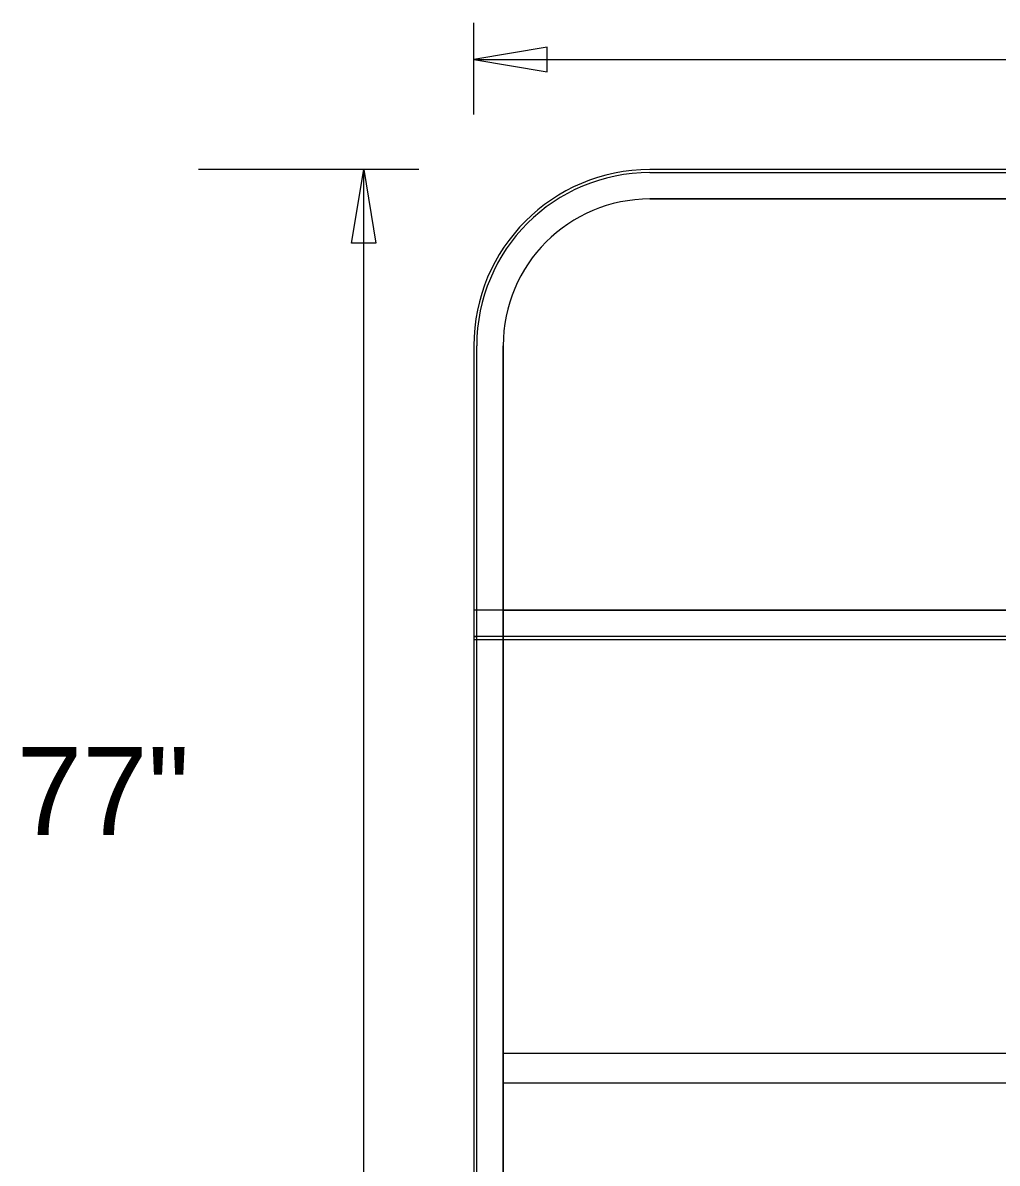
# Model space of a CAD drawing. Extents: x 119523 to 121850, y -23542 to -19972.
# Drawn here: x 120147.5 to 120213.9, y -22898.6 to -22820.9 of the extents above; entities that cross this region are included whole.
import ezdxf

# ---------------------------------------------------------------- set-up
doc = ezdxf.new("R2010")
doc.units = 0
for name, color, linetype in [('GSBWFill', 7, 'Continuous'), ('GSColorFill', 7, 'Continuous'), ('GSDims', 7, 'Continuous'), ('GSOutline', 7, 'Continuous')]:
    doc.layers.add(name, color=color, linetype=linetype)

msp = doc.modelspace()

# ---------------------------------------------------------------- linework, layer by layer
at = {"layer": 'GSBWFill'}
for p, q in [((120424.249, -22830.872), (120190.249, -22830.872)), ((120424.249, -22830.872), (120190.249, -22830.872)), ((120190.249, -22832.872), (120424.249, -22832.872)), ((120190.249, -22832.872), (120424.249, -22832.872)), ((120178.249, -22842.872), (120178.249, -22974.872)), ((120178.249, -22842.872), (120178.249, -22860.852)), ((120180.249, -22974.872), (120180.249, -22842.872)), ((120180.249, -22860.852), (120180.249, -22842.872)), ((120178.249, -22860.852), (120180.249, -22860.852)), ((120434.249, -22860.872), (120178.249, -22860.872)), ((120178.249, -22860.872), (120178.249, -22862.872)), ((120178.249, -22862.872), (120436.249, -22862.872)), ((120434.249, -22891.075), (120180.249, -22891.075)), ((120180.249, -22891.075), (120180.249, -22893.075)), ((120180.249, -22893.075), (120434.249, -22893.075))]:
    msp.add_line(p, q, dxfattribs=at)
for radius in [12, 12, 10, 10]:
    msp.add_arc((120190.249, -22842.872), radius, 90, 180, dxfattribs=at)
at = {"layer": 'GSColorFill'}
for p, q in [((120424.249, -22830.872), (120190.249, -22830.872)), ((120424.249, -22830.872), (120190.249, -22830.872)), ((120424.249, -22830.872), (120190.249, -22830.872)), ((120424.249, -22830.872), (120190.249, -22830.872)), ((120424.249, -22830.872), (120190.249, -22830.872)), ((120424.249, -22830.872), (120190.249, -22830.872)), ((120190.249, -22831.072), (120424.249, -22831.072)), ((120190.249, -22831.072), (120424.249, -22831.072)), ((120190.249, -22832.872), (120424.249, -22832.872)), ((120190.249, -22832.872), (120424.249, -22832.872)), ((120178.249, -22842.872), (120178.249, -22974.872)), ((120178.249, -22842.872), (120178.249, -22974.872)), ((120178.249, -22842.872), (120178.249, -22974.872)), ((120178.249, -22842.872), (120178.249, -22862.872)), ((120178.249, -22842.872), (120178.249, -22860.852)), ((120178.249, -22842.872), (120178.249, -22862.67)), ((120178.449, -22974.872), (120178.449, -22842.872)), ((120178.449, -22862.67), (120178.449, -22842.872)), ((120180.249, -22974.872), (120180.249, -22842.872)), ((120180.249, -22860.852), (120180.249, -22842.872)), ((120178.249, -22860.852), (120180.249, -22860.852)), ((120434.249, -22860.872), (120178.249, -22860.872)), ((120178.249, -22860.872), (120178.249, -22862.872)), ((120178.249, -22862.67), (120178.449, -22862.67)), ((120436.049, -22862.672), (120178.249, -22862.672)), ((120178.249, -22862.672), (120178.249, -22862.872)), ((120178.249, -22862.872), (120436.249, -22862.872)), ((120178.249, -22862.872), (120436.249, -22862.872)), ((120178.249, -22862.872), (120436.249, -22862.872)), ((120434.249, -22891.075), (120180.249, -22891.075)), ((120180.249, -22891.075), (120180.249, -22893.075)), ((120180.249, -22893.075), (120434.249, -22893.075))]:
    msp.add_line(p, q, dxfattribs=at)
for radius in [12, 12, 12, 12, 12, 12, 11.8, 11.8, 10, 10]:
    msp.add_arc((120190.249, -22842.872), radius, 90, 180, dxfattribs=at)
at = {"layer": 'GSDims'}
for p, q in [((120178.249, -22827.122), (120178.249, -22820.872)), ((120178.249, -22823.372), (120436.249, -22823.372)), ((120178.249, -22827.122), (120178.249, -22827.122)), ((120174.499, -22830.872), (120159.499, -22830.872)), ((120174.499, -22830.872), (120168.249, -22830.872)), ((120170.749, -22907.826), (120170.749, -22830.872))]:
    msp.add_line(p, q, dxfattribs=at)
for points in [[(120178.249, -22823.372), (120183.249, -22824.205), (120183.249, -22822.538)], [(120170.749, -22830.872), (120171.582, -22835.872), (120169.915, -22835.872)]]:
    msp.add_lwpolyline(points, close=True, dxfattribs=at)
at = {"layer": 'GSOutline'}
for p, q in [((120424.249, -22830.872), (120190.249, -22830.872)), ((120424.249, -22830.872), (120190.249, -22830.872)), ((120424.249, -22832.872), (120190.249, -22832.872)), ((120424.249, -22832.872), (120190.249, -22832.872)), ((120178.249, -22842.872), (120178.249, -22974.872)), ((120178.249, -22842.872), (120178.249, -22862.872)), ((120180.249, -22842.872), (120180.249, -22974.872)), ((120180.249, -22842.872), (120180.249, -22860.872)), ((120180.249, -22860.872), (120434.249, -22860.872)), ((120178.249, -22862.872), (120436.249, -22862.872)), ((120434.249, -22891.075), (120180.249, -22891.075)), ((120180.249, -22891.075), (120180.249, -22893.075)), ((120180.249, -22893.075), (120434.249, -22893.075))]:
    msp.add_line(p, q, dxfattribs=at)
for radius in [12, 12, 10, 10]:
    msp.add_arc((120190.249, -22842.872), radius, 90, 180, dxfattribs=at)

# ---------------------------------------------------------------- texts
at = {"layer": 'GSDims'}
msp.add_text('77"', height=6, dxfattribs=at).set_placement((120147.11, -22876.203))

doc.saveas('drawing.dxf')
